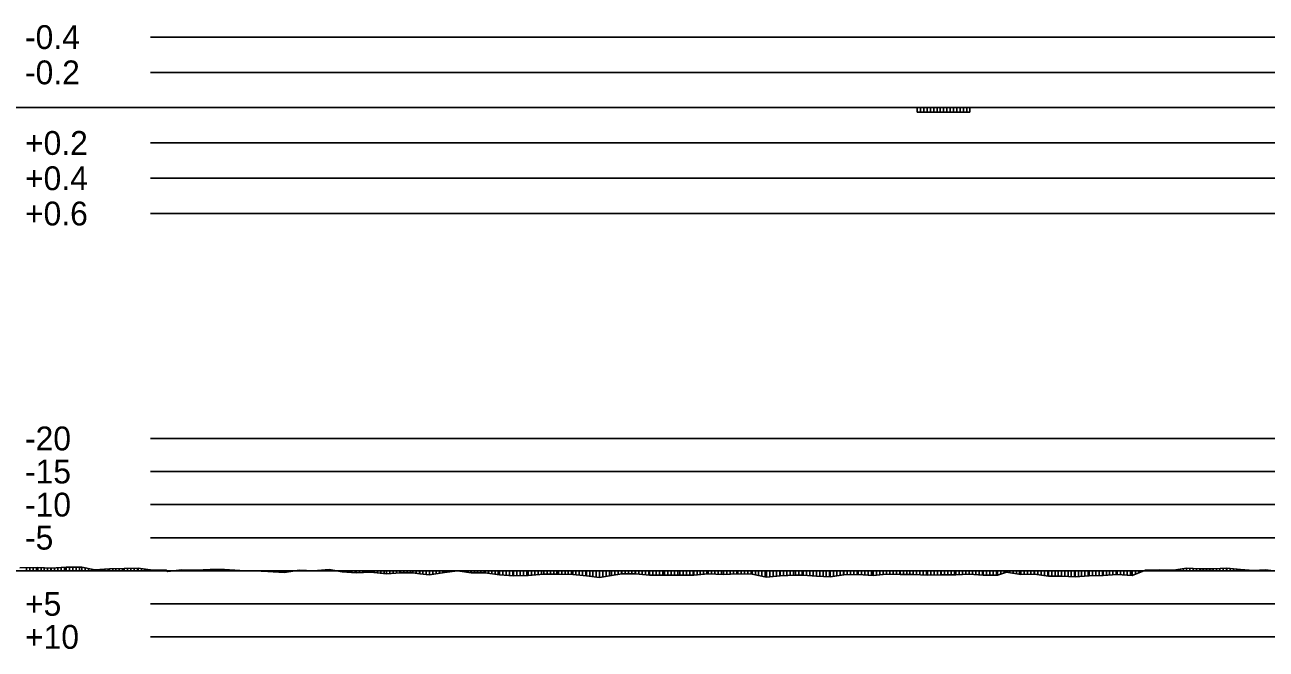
# Model space of a CAD drawing. Extents: x 2 to 10148, y 0 to 380.
# Drawn here: x 1152.5 to 1246.3, y 236.1 to 283.3 of the extents above; entities that cross this region are included whole.
import ezdxf

# ---------------------------------------------------------------- set-up
doc = ezdxf.new("R2010")
doc.units = 0
for name, color, linetype in [('POSUN_CARA', 7, 'Continuous'), ('POSUN_RASTR', 7, 'Continuous'), ('POSUN_TEXT', 7, 'Continuous'), ('ZRYCHL_CARA', 7, 'Continuous'), ('ZRYCHL_RASTR', 7, 'Continuous'), ('ZRYCHL_TEXT', 7, 'Continuous')]:
    doc.layers.add(name, color=color, linetype=linetype)

msp = doc.modelspace()

# ---------------------------------------------------------------- linework, layer by layer
at = {"layer": 'POSUN_CARA'}
for p, q in [((1152.119, 242.222), (1153.461, 242.257)), ((1152.619, 242), (1152.619, 242.235)), ((1152.869, 242), (1152.869, 242.241)), ((1153.119, 242), (1153.119, 242.248)), ((1153.369, 242), (1153.369, 242.255)), ((1153.461, 242.257), (1154.491, 242.196)), ((1153.461, 242), (1153.461, 242.257)), ((1153.711, 242), (1153.711, 242.242)), ((1153.961, 242), (1153.961, 242.227)), ((1154.211, 242), (1154.211, 242.213)), ((1154.461, 242), (1154.461, 242.198)), ((1154.491, 242.196), (1155.615, 242.273)), ((1154.491, 242), (1154.491, 242.196)), ((1154.741, 242), (1154.741, 242.213)), ((1154.991, 242), (1154.991, 242.23)), ((1155.241, 242), (1155.241, 242.248)), ((1155.491, 242), (1155.491, 242.265)), ((1155.615, 242.273), (1156.802, 242.264)), ((1155.615, 242), (1155.615, 242.273)), ((1155.865, 242), (1155.865, 242.271)), ((1156.115, 242), (1156.115, 242.269)), ((1156.365, 242), (1156.365, 242.267)), ((1156.615, 242), (1156.615, 242.265)), ((1156.802, 242.264), (1157.792, 242.077)), ((1156.802, 242), (1156.802, 242.264)), ((1157.052, 242), (1157.052, 242.217)), ((1157.302, 242), (1157.302, 242.169)), ((1157.792, 242.077), (1158.88, 242.143)), ((1158.88, 242.143), (1160.011, 242.176)), ((1158.88, 242), (1158.88, 242.143)), ((1159.13, 242), (1159.13, 242.15)), ((1159.38, 242), (1159.38, 242.158)), ((1159.63, 242), (1159.63, 242.165)), ((1159.88, 242), (1159.88, 242.172)), ((1160.011, 242.176), (1161.067, 242.202)), ((1160.011, 242), (1160.011, 242.176)), ((1160.261, 242), (1160.261, 242.182)), ((1160.511, 242), (1160.511, 242.189)), ((1160.761, 242), (1160.761, 242.195)), ((1161.011, 242), (1161.011, 242.201)), ((1161.067, 242.202), (1162.167, 242.055)), ((1161.067, 242), (1161.067, 242.202)), ((1161.317, 242), (1161.317, 242.169)), ((1239.345, 242.049), (1240.321, 242.202)), ((1240.095, 242), (1240.095, 242.166)), ((1240.321, 242.202), (1241.34, 242.158)), ((1240.321, 242), (1240.321, 242.202)), ((1240.571, 242), (1240.571, 242.191)), ((1240.821, 242), (1240.821, 242.18)), ((1241.071, 242), (1241.071, 242.169)), ((1241.321, 242), (1241.321, 242.159)), ((1241.34, 242.158), (1242.332, 242.151)), ((1241.34, 242), (1241.34, 242.158)), ((1241.59, 242), (1241.59, 242.156)), ((1241.84, 242), (1241.84, 242.155)), ((1242.09, 242), (1242.09, 242.153)), ((1242.332, 242.151), (1243.366, 242.19)), ((1242.332, 242), (1242.332, 242.151)), ((1242.582, 242), (1242.582, 242.161)), ((1242.832, 242), (1242.832, 242.17)), ((1243.082, 242), (1243.082, 242.179)), ((1243.332, 242), (1243.332, 242.189)), ((1243.366, 242.19), (1244.404, 242.103)), ((1243.366, 242), (1243.366, 242.19)), ((1243.616, 242), (1243.616, 242.169)), ((1243.866, 242), (1243.866, 242.148)), ((1157.552, 242), (1157.552, 242.122)), ((1157.792, 242), (1157.792, 242.077)), ((1158.042, 242), (1158.042, 242.092)), ((1158.292, 242), (1158.292, 242.107)), ((1158.542, 242), (1158.542, 242.122)), ((1158.792, 242), (1158.792, 242.137)), ((1161.567, 242), (1161.567, 242.135)), ((1161.817, 242), (1161.817, 242.102)), ((1162.067, 242), (1162.067, 242.069)), ((1162.167, 242.055), (1163.171, 242.071)), ((1162.167, 242), (1162.167, 242.055)), ((1162.417, 242), (1162.417, 242.059)), ((1162.667, 242), (1162.667, 242.063)), ((1162.917, 242), (1162.917, 242.067)), ((1163.167, 242), (1163.167, 242.071)), ((1163.171, 242.071), (1163.174, 241.999)), ((1163.171, 242), (1163.171, 242.071)), ((1163.233, 241.988), (1163.235, 242.031)), ((1163.233, 242), (1163.233, 241.988)), ((1163.235, 242.031), (1163.291, 241.925)), ((1163.235, 242), (1163.235, 242.031)), ((1163.291, 242), (1163.291, 241.925)), ((1163.291, 241.925), (1163.293, 241.95)), ((1163.293, 241.95), (1164.322, 242.082)), ((1163.293, 242), (1163.293, 241.95)), ((1163.543, 242), (1163.543, 241.982)), ((1163.793, 242), (1163.793, 242.014)), ((1164.043, 242), (1164.043, 242.046)), ((1164.293, 242), (1164.293, 242.078)), ((1164.322, 242.082), (1165.443, 242.052)), ((1164.322, 242), (1164.322, 242.082)), ((1164.572, 242), (1164.572, 242.075)), ((1164.822, 242), (1164.822, 242.069)), ((1165.072, 242), (1165.072, 242.062)), ((1165.322, 242), (1165.322, 242.055)), ((1165.443, 242.052), (1166.513, 242.103)), ((1165.443, 242), (1165.443, 242.052)), ((1165.693, 242), (1165.693, 242.064)), ((1165.943, 242), (1165.943, 242.076)), ((1166.193, 242), (1166.193, 242.088)), ((1166.443, 242), (1166.443, 242.1)), ((1166.513, 242.103), (1167.573, 242.097)), ((1166.513, 242), (1166.513, 242.103)), ((1166.763, 242), (1166.763, 242.102)), ((1167.013, 242), (1167.013, 242.1)), ((1167.263, 242), (1167.263, 242.099)), ((1167.513, 242), (1167.513, 242.098)), ((1167.573, 242.097), (1168.735, 242.013)), ((1167.573, 242), (1167.573, 242.097)), ((1167.823, 242), (1167.823, 242.079)), ((1168.073, 242), (1168.073, 242.061)), ((1168.323, 242), (1168.323, 242.043)), ((1168.573, 242), (1168.573, 242.025)), ((1169.835, 242), (1169.835, 241.989)), ((1169.835, 241.989), (1170.85, 241.936)), ((1170.085, 242), (1170.085, 241.976)), ((1170.335, 242), (1170.335, 241.963)), ((1170.585, 242), (1170.585, 241.95)), ((1170.835, 242), (1170.835, 241.937)), ((1170.85, 242), (1170.85, 241.936)), ((1170.85, 241.936), (1172.106, 241.873)), ((1171.1, 242), (1171.1, 241.923)), ((1171.35, 242), (1171.35, 241.911)), ((1171.6, 242), (1171.6, 241.898)), ((1171.85, 242), (1171.85, 241.886)), ((1172.1, 242), (1172.1, 241.873)), ((1172.106, 241.873), (1173.244, 242.053)), ((1172.106, 242), (1172.106, 241.873)), ((1172.356, 242), (1172.356, 241.913)), ((1172.606, 242), (1172.606, 241.952)), ((1172.856, 242), (1172.856, 241.992)), ((1173.106, 242), (1173.106, 242.032)), ((1173.244, 242.053), (1174.312, 241.999)), ((1173.244, 242), (1173.244, 242.053)), ((1173.494, 242), (1173.494, 242.041)), ((1173.744, 242), (1173.744, 242.028)), ((1173.994, 242), (1173.994, 242.015)), ((1174.244, 242), (1174.244, 242.002)), ((1174.312, 241.999), (1175.497, 242.089)), ((1174.312, 242), (1174.312, 241.999)), ((1174.562, 242), (1174.562, 242.018)), ((1174.812, 242), (1174.812, 242.037)), ((1175.062, 242), (1175.062, 242.056)), ((1175.312, 242), (1175.312, 242.075)), ((1175.497, 242.089), (1176.472, 241.911)), ((1175.497, 242), (1175.497, 242.089)), ((1175.747, 242), (1175.747, 242.044)), ((1175.997, 242), (1175.997, 241.998)), ((1176.247, 242), (1176.247, 241.952)), ((1176.472, 242), (1176.472, 241.911)), ((1176.472, 241.911), (1177.546, 241.846)), ((1176.722, 242), (1176.722, 241.896)), ((1176.972, 242), (1176.972, 241.88)), ((1177.222, 242), (1177.222, 241.865)), ((1177.472, 242), (1177.472, 241.85)), ((1177.546, 242), (1177.546, 241.846)), ((1177.546, 241.846), (1178.659, 241.901)), ((1177.796, 242), (1177.796, 241.858)), ((1178.046, 242), (1178.046, 241.871)), ((1178.296, 242), (1178.296, 241.883)), ((1178.546, 242), (1178.546, 241.896)), ((1178.659, 242), (1178.659, 241.901)), ((1178.659, 241.901), (1179.83, 241.759)), ((1178.909, 242), (1178.909, 241.871)), ((1179.159, 242), (1179.159, 241.841)), ((1179.409, 242), (1179.409, 241.81)), ((1179.659, 242), (1179.659, 241.78)), ((1179.83, 242), (1179.83, 241.759)), ((1179.83, 241.759), (1180.889, 241.847)), ((1180.08, 242), (1180.08, 241.78)), ((1180.33, 242), (1180.33, 241.8)), ((1180.58, 242), (1180.58, 241.821)), ((1180.83, 242), (1180.83, 241.842)), ((1180.889, 242), (1180.889, 241.847)), ((1180.889, 241.847), (1181.816, 241.832)), ((1181.139, 242), (1181.139, 241.843)), ((1181.389, 242), (1181.389, 241.839)), ((1181.639, 242), (1181.639, 241.835)), ((1181.816, 242), (1181.816, 241.832)), ((1181.816, 241.832), (1182.342, 241.768)), ((1182.066, 242), (1182.066, 241.801)), ((1182.316, 242), (1182.316, 241.771)), ((1182.342, 242), (1182.342, 241.768)), ((1182.342, 241.768), (1183.092, 241.692)), ((1182.592, 242), (1182.592, 241.742)), ((1182.842, 242), (1182.842, 241.717)), ((1183.092, 242), (1183.092, 241.692)), ((1183.092, 241.692), (1184.21, 241.863)), ((1183.342, 242), (1183.342, 241.73)), ((1183.592, 242), (1183.592, 241.769)), ((1183.842, 242), (1183.842, 241.807)), ((1184.092, 242), (1184.092, 241.845)), ((1184.21, 242), (1184.21, 241.863)), ((1184.21, 241.863), (1185.201, 241.986)), ((1184.46, 242), (1184.46, 241.894)), ((1184.71, 242), (1184.71, 241.925)), ((1184.96, 242), (1184.96, 241.956)), ((1185.201, 242), (1185.201, 241.986)), ((1185.201, 241.986), (1186.225, 241.838)), ((1185.451, 242), (1185.451, 241.95)), ((1185.701, 242), (1185.701, 241.914)), ((1185.951, 242), (1185.951, 241.877)), ((1186.201, 242), (1186.201, 241.841)), ((1186.225, 242), (1186.225, 241.838)), ((1186.225, 241.838), (1187.286, 241.849)), ((1186.475, 242), (1186.475, 241.841)), ((1186.725, 242), (1186.725, 241.843)), ((1186.975, 242), (1186.975, 241.846)), ((1187.225, 242), (1187.225, 241.848)), ((1187.286, 242), (1187.286, 241.849)), ((1187.286, 241.849), (1188.377, 241.688)), ((1187.536, 242), (1187.536, 241.812)), ((1187.786, 242), (1187.786, 241.775)), ((1188.036, 242), (1188.036, 241.738)), ((1188.286, 242), (1188.286, 241.701)), ((1188.377, 242), (1188.377, 241.688)), ((1188.377, 241.688), (1189.431, 241.611)), ((1188.627, 242), (1188.627, 241.67)), ((1188.877, 242), (1188.877, 241.651)), ((1189.127, 242), (1189.127, 241.633)), ((1189.377, 242), (1189.377, 241.615)), ((1189.431, 242), (1189.431, 241.611)), ((1189.431, 241.611), (1190.541, 241.653)), ((1189.681, 242), (1189.681, 241.62)), ((1189.931, 242), (1189.931, 241.63)), ((1190.181, 242), (1190.181, 241.639)), ((1190.431, 242), (1190.431, 241.649)), ((1190.541, 242), (1190.541, 241.653)), ((1190.541, 241.653), (1191.722, 241.743)), ((1190.791, 242), (1190.791, 241.672)), ((1191.041, 242), (1191.041, 241.691)), ((1191.291, 242), (1191.291, 241.71)), ((1191.541, 242), (1191.541, 241.729)), ((1191.722, 242), (1191.722, 241.743)), ((1191.722, 241.743), (1192.829, 241.738)), ((1191.972, 242), (1191.972, 241.742)), ((1192.222, 242), (1192.222, 241.741)), ((1192.472, 242), (1192.472, 241.74)), ((1192.722, 242), (1192.722, 241.739)), ((1192.829, 242), (1192.829, 241.738)), ((1192.829, 241.738), (1193.909, 241.707)), ((1193.079, 242), (1193.079, 241.731)), ((1193.329, 242), (1193.329, 241.724)), ((1193.579, 242), (1193.579, 241.716)), ((1193.829, 242), (1193.829, 241.709)), ((1193.909, 242), (1193.909, 241.707)), ((1193.909, 241.707), (1194.944, 241.626)), ((1194.159, 242), (1194.159, 241.687)), ((1194.409, 242), (1194.409, 241.668)), ((1194.659, 242), (1194.659, 241.649)), ((1194.909, 242), (1194.909, 241.629)), ((1194.944, 242), (1194.944, 241.626)), ((1194.944, 241.626), (1195.939, 241.492)), ((1195.194, 242), (1195.194, 241.593)), ((1195.444, 242), (1195.444, 241.559)), ((1195.694, 242), (1195.694, 241.525)), ((1195.939, 242), (1195.939, 241.492)), ((1195.939, 241.492), (1196.848, 241.647)), ((1196.189, 242), (1196.189, 241.535)), ((1196.439, 242), (1196.439, 241.577)), ((1196.689, 242), (1196.689, 241.62)), ((1196.848, 242), (1196.848, 241.647)), ((1196.848, 241.647), (1197.627, 241.768)), ((1197.098, 242), (1197.098, 241.686)), ((1197.348, 242), (1197.348, 241.724)), ((1197.598, 242), (1197.598, 241.763)), ((1197.627, 242), (1197.627, 241.768)), ((1197.627, 241.768), (1198.657, 241.761)), ((1197.877, 242), (1197.877, 241.766)), ((1198.127, 242), (1198.127, 241.764)), ((1198.377, 242), (1198.377, 241.763)), ((1198.627, 242), (1198.627, 241.761)), ((1198.657, 242), (1198.657, 241.761)), ((1198.657, 241.761), (1199.723, 241.666)), ((1198.907, 242), (1198.907, 241.738)), ((1199.157, 242), (1199.157, 241.716)), ((1199.407, 242), (1199.407, 241.694)), ((1199.657, 242), (1199.657, 241.672)), ((1199.723, 242), (1199.723, 241.666)), ((1199.723, 241.666), (1200.848, 241.663)), ((1199.973, 242), (1199.973, 241.665)), ((1200.223, 242), (1200.223, 241.664)), ((1200.473, 242), (1200.473, 241.664)), ((1200.723, 242), (1200.723, 241.663)), ((1200.848, 242), (1200.848, 241.663)), ((1200.848, 241.663), (1202.016, 241.665)), ((1201.098, 242), (1201.098, 241.663)), ((1201.348, 242), (1201.348, 241.664)), ((1201.598, 242), (1201.598, 241.664)), ((1201.848, 242), (1201.848, 241.664)), ((1202.016, 242), (1202.016, 241.665)), ((1202.016, 241.665), (1203.059, 241.665)), ((1202.266, 242), (1202.266, 241.665)), ((1202.516, 242), (1202.516, 241.665)), ((1202.766, 242), (1202.766, 241.665)), ((1203.016, 242), (1203.016, 241.665)), ((1203.059, 242), (1203.059, 241.665)), ((1203.059, 241.665), (1204.163, 241.774)), ((1203.309, 242), (1203.309, 241.69)), ((1203.559, 242), (1203.559, 241.715)), ((1203.809, 242), (1203.809, 241.739)), ((1204.059, 242), (1204.059, 241.764)), ((1204.163, 242), (1204.163, 241.774)), ((1204.163, 241.774), (1205.317, 241.708)), ((1204.413, 242), (1204.413, 241.76)), ((1204.663, 242), (1204.663, 241.746)), ((1204.913, 242), (1204.913, 241.731)), ((1205.163, 242), (1205.163, 241.717)), ((1205.317, 242), (1205.317, 241.708)), ((1205.317, 241.708), (1206.4, 241.776)), ((1205.567, 242), (1205.567, 241.724)), ((1205.817, 242), (1205.817, 241.739)), ((1206.067, 242), (1206.067, 241.755)), ((1206.317, 242), (1206.317, 241.77)), ((1206.4, 242), (1206.4, 241.776)), ((1206.4, 241.776), (1207.469, 241.745)), ((1206.65, 242), (1206.65, 241.768)), ((1206.9, 242), (1206.9, 241.761)), ((1207.15, 242), (1207.15, 241.754)), ((1207.4, 242), (1207.4, 241.747)), ((1207.469, 242), (1207.469, 241.745)), ((1207.469, 241.745), (1208.57, 241.528)), ((1207.719, 242), (1207.719, 241.695)), ((1207.969, 242), (1207.969, 241.646)), ((1208.219, 242), (1208.219, 241.597)), ((1208.469, 242), (1208.469, 241.548)), ((1208.57, 242), (1208.57, 241.528)), ((1208.57, 241.528), (1209.606, 241.616)), ((1208.82, 242), (1208.82, 241.549)), ((1209.07, 242), (1209.07, 241.57)), ((1209.32, 242), (1209.32, 241.592)), ((1209.57, 242), (1209.57, 241.613)), ((1209.606, 242), (1209.606, 241.616)), ((1209.606, 241.616), (1210.755, 241.664)), ((1209.856, 242), (1209.856, 241.626)), ((1210.106, 242), (1210.106, 241.637)), ((1210.356, 242), (1210.356, 241.647)), ((1210.606, 242), (1210.606, 241.658)), ((1210.755, 242), (1210.755, 241.664)), ((1210.755, 241.664), (1211.331, 241.669)), ((1211.005, 242), (1211.005, 241.666)), ((1211.255, 242), (1211.255, 241.669)), ((1211.331, 242), (1211.331, 241.669)), ((1211.331, 241.669), (1212.335, 241.594)), ((1211.581, 242), (1211.581, 241.65)), ((1211.831, 242), (1211.831, 241.632)), ((1212.081, 242), (1212.081, 241.613)), ((1212.331, 242), (1212.331, 241.594)), ((1212.335, 242), (1212.335, 241.594)), ((1212.335, 241.594), (1213.38, 241.547)), ((1212.585, 242), (1212.585, 241.583)), ((1212.835, 242), (1212.835, 241.571)), ((1213.085, 242), (1213.085, 241.56)), ((1213.335, 242), (1213.335, 241.549)), ((1213.38, 242), (1213.38, 241.547)), ((1213.38, 241.547), (1214.422, 241.699)), ((1213.63, 242), (1213.63, 241.583)), ((1213.88, 242), (1213.88, 241.62)), ((1214.13, 242), (1214.13, 241.657)), ((1214.38, 242), (1214.38, 241.693)), ((1214.422, 242), (1214.422, 241.699)), ((1214.422, 241.699), (1215.503, 241.714)), ((1214.672, 242), (1214.672, 241.703)), ((1214.922, 242), (1214.922, 241.706)), ((1215.172, 242), (1215.172, 241.709)), ((1215.422, 242), (1215.422, 241.712)), ((1215.503, 242), (1215.503, 241.714)), ((1215.503, 241.714), (1216.626, 241.631)), ((1215.753, 242), (1215.753, 241.695)), ((1216.003, 242), (1216.003, 241.677)), ((1216.253, 242), (1216.253, 241.659)), ((1216.503, 242), (1216.503, 241.64)), ((1216.626, 242), (1216.626, 241.631)), ((1216.626, 241.631), (1217.638, 241.754)), ((1216.876, 242), (1216.876, 241.662)), ((1217.126, 242), (1217.126, 241.692)), ((1217.376, 242), (1217.376, 241.723)), ((1217.626, 242), (1217.626, 241.753)), ((1217.638, 242), (1217.638, 241.754)), ((1217.638, 241.754), (1218.661, 241.719)), ((1217.888, 242), (1217.888, 241.746)), ((1218.138, 242), (1218.138, 241.737)), ((1218.388, 242), (1218.388, 241.729)), ((1218.638, 242), (1218.638, 241.72)), ((1218.661, 242), (1218.661, 241.719)), ((1218.661, 241.719), (1219.657, 241.708)), ((1218.911, 242), (1218.911, 241.717)), ((1219.161, 242), (1219.161, 241.714)), ((1219.411, 242), (1219.411, 241.711)), ((1219.657, 242), (1219.657, 241.708)), ((1219.657, 241.708), (1220.735, 241.663)), ((1219.907, 242), (1219.907, 241.698)), ((1220.157, 242), (1220.157, 241.687)), ((1220.407, 242), (1220.407, 241.677)), ((1220.657, 242), (1220.657, 241.667)), ((1220.735, 242), (1220.735, 241.663)), ((1220.735, 241.663), (1221.779, 241.692)), ((1220.985, 242), (1220.985, 241.67)), ((1221.235, 242), (1221.235, 241.677)), ((1221.485, 242), (1221.485, 241.684)), ((1221.735, 242), (1221.735, 241.691)), ((1221.779, 242), (1221.779, 241.692)), ((1221.779, 241.692), (1222.886, 241.696)), ((1222.029, 242), (1222.029, 241.693)), ((1222.279, 242), (1222.279, 241.693)), ((1222.529, 242), (1222.529, 241.694)), ((1222.779, 242), (1222.779, 241.695)), ((1222.886, 242), (1222.886, 241.696)), ((1222.886, 241.696), (1223.887, 241.735)), ((1223.136, 242), (1223.136, 241.706)), ((1223.386, 242), (1223.386, 241.715)), ((1223.636, 242), (1223.636, 241.725)), ((1223.886, 242), (1223.886, 241.735)), ((1223.887, 242), (1223.887, 241.735)), ((1223.887, 241.735), (1224.943, 241.655)), ((1224.137, 242), (1224.137, 241.716)), ((1224.387, 242), (1224.387, 241.697)), ((1224.637, 242), (1224.637, 241.678)), ((1224.887, 242), (1224.887, 241.659)), ((1224.943, 242), (1224.943, 241.655)), ((1224.943, 241.655), (1226.022, 241.669)), ((1225.193, 242), (1225.193, 241.658)), ((1225.443, 242), (1225.443, 241.661)), ((1225.693, 242), (1225.693, 241.665)), ((1225.943, 242), (1225.943, 241.668)), ((1226.022, 242), (1226.022, 241.669)), ((1226.022, 241.669), (1226.703, 241.884)), ((1226.272, 242), (1226.272, 241.748)), ((1226.522, 242), (1226.522, 241.827)), ((1226.703, 242), (1226.703, 241.884)), ((1226.703, 241.884), (1227.788, 241.709)), ((1226.953, 242), (1226.953, 241.844)), ((1227.203, 242), (1227.203, 241.803)), ((1227.453, 242), (1227.453, 241.763)), ((1227.703, 242), (1227.703, 241.722)), ((1227.788, 242), (1227.788, 241.709)), ((1227.788, 241.709), (1228.836, 241.734)), ((1228.038, 242), (1228.038, 241.715)), ((1228.288, 242), (1228.288, 241.721)), ((1228.538, 242), (1228.538, 241.727)), ((1228.788, 242), (1228.788, 241.733)), ((1228.836, 242), (1228.836, 241.734)), ((1228.836, 241.734), (1229.877, 241.602)), ((1229.086, 242), (1229.086, 241.702)), ((1229.336, 242), (1229.336, 241.671)), ((1229.586, 242), (1229.586, 241.639)), ((1229.836, 242), (1229.836, 241.607)), ((1229.877, 242), (1229.877, 241.602)), ((1229.877, 241.602), (1230.859, 241.594)), ((1230.127, 242), (1230.127, 241.6)), ((1230.377, 242), (1230.377, 241.598)), ((1230.627, 242), (1230.627, 241.596)), ((1230.859, 242), (1230.859, 241.594)), ((1230.859, 241.594), (1231.89, 241.533)), ((1231.109, 242), (1231.109, 241.579)), ((1231.359, 242), (1231.359, 241.564)), ((1231.609, 242), (1231.609, 241.55)), ((1231.859, 242), (1231.859, 241.535)), ((1231.89, 242), (1231.89, 241.533)), ((1231.89, 241.533), (1232.958, 241.626)), ((1232.14, 242), (1232.14, 241.555)), ((1232.39, 242), (1232.39, 241.577)), ((1232.64, 242), (1232.64, 241.599)), ((1232.89, 242), (1232.89, 241.621)), ((1232.958, 242), (1232.958, 241.626)), ((1232.958, 241.626), (1234.008, 241.641)), ((1233.208, 242), (1233.208, 241.63)), ((1233.458, 242), (1233.458, 241.633)), ((1233.708, 242), (1233.708, 241.636)), ((1233.958, 242), (1233.958, 241.64)), ((1234.008, 242), (1234.008, 241.641)), ((1234.008, 241.641), (1235.073, 241.73)), ((1234.258, 242), (1234.258, 241.662)), ((1234.508, 242), (1234.508, 241.682)), ((1234.758, 242), (1234.758, 241.703)), ((1235.008, 242), (1235.008, 241.724)), ((1235.073, 242), (1235.073, 241.73)), ((1235.073, 241.73), (1236.212, 241.654)), ((1235.323, 242), (1235.323, 241.713)), ((1235.573, 242), (1235.573, 241.697)), ((1235.823, 242), (1235.823, 241.68)), ((1236.073, 242), (1236.073, 241.664)), ((1236.212, 241.654), (1237.218, 242.055)), ((1236.212, 242), (1236.212, 241.654)), ((1236.462, 242), (1236.462, 241.754)), ((1236.712, 242), (1236.712, 241.854)), ((1236.962, 242), (1236.962, 241.953)), ((1237.212, 242), (1237.212, 242.053)), ((1237.218, 242.055), (1238.239, 242.066)), ((1237.218, 242), (1237.218, 242.055)), ((1237.468, 242), (1237.468, 242.058)), ((1237.718, 242), (1237.718, 242.061)), ((1237.968, 242), (1237.968, 242.063)), ((1238.218, 242), (1238.218, 242.066)), ((1238.239, 242.066), (1239.345, 242.049)), ((1238.239, 242), (1238.239, 242.066)), ((1238.489, 242), (1238.489, 242.062)), ((1238.739, 242), (1238.739, 242.058)), ((1238.989, 242), (1238.989, 242.054)), ((1239.239, 242), (1239.239, 242.05)), ((1239.345, 242), (1239.345, 242.049)), ((1239.595, 242), (1239.595, 242.088)), ((1239.845, 242), (1239.845, 242.127)), ((1244.116, 242), (1244.116, 242.127)), ((1244.366, 242), (1244.366, 242.106)), ((1244.404, 242.103), (1245.395, 242.023)), ((1244.404, 242), (1244.404, 242.103)), ((1244.654, 242), (1244.654, 242.083)), ((1244.904, 242), (1244.904, 242.062)), ((1245.154, 242), (1245.154, 242.042)), ((1245.39, 242.023), (1246.27, 242.066)), ((1245.39, 242), (1245.39, 242.023)), ((1245.64, 242), (1245.64, 242.035)), ((1245.89, 242), (1245.89, 242.047)), ((1246.14, 242), (1246.14, 242.06)), ((1246.27, 242.066), (1247.142, 241.975)), ((1246.27, 242), (1246.27, 242.066))]:
    msp.add_line(p, q, dxfattribs=at)
at = {"layer": 'POSUN_RASTR'}
for p, q in [((1162, 252), (1245.395, 252)), ((1245.39, 252), (1358, 252)), ((1162, 249.5), (1245.395, 249.5)), ((1245.39, 249.5), (1358, 249.5)), ((1162, 247), (1245.395, 247)), ((1245.39, 247), (1358, 247)), ((1162, 244.5), (1245.395, 244.5)), ((1245.39, 244.5), (1358, 244.5)), ((631.22, 242), (1245.395, 242)), ((1245.39, 242), (1850.829, 242)), ((1162, 239.5), (1245.395, 239.5)), ((1245.39, 239.5), (1358, 239.5)), ((1162, 237), (1245.395, 237)), ((1245.39, 237), (1358, 237))]:
    msp.add_line(p, q, dxfattribs=at)
at = {"layer": 'ZRYCHL_CARA'}
for p, q in [((631.22, 277), (1245.395, 277)), ((1219.954, 277), (1219.954, 276.672)), ((1219.954, 277), (1219.954, 276.672)), ((1220.204, 277), (1220.204, 276.672)), ((1220.454, 277), (1220.454, 276.672)), ((1220.704, 277), (1220.704, 276.672)), ((1220.954, 277), (1220.954, 276.672)), ((1221.204, 277), (1221.204, 276.672)), ((1221.454, 277), (1221.454, 276.672)), ((1221.704, 277), (1221.704, 276.672)), ((1221.954, 277), (1221.954, 276.672)), ((1222.204, 277), (1222.204, 276.672)), ((1222.454, 277), (1222.454, 276.672)), ((1222.704, 277), (1222.704, 276.672)), ((1222.954, 277), (1222.954, 276.672)), ((1223.204, 277), (1223.204, 276.672)), ((1223.454, 277), (1223.454, 276.672)), ((1223.704, 277), (1223.704, 276.672)), ((1223.924, 276.672), (1223.924, 277)), ((1245.39, 277), (1850.829, 277)), ((1219.954, 276.672), (1223.924, 276.672))]:
    msp.add_line(p, q, dxfattribs=at)
at = {"layer": 'ZRYCHL_RASTR'}
for p, q in [((1162, 282.333), (1245.395, 282.333)), ((1245.39, 282.333), (1369.417, 282.333)), ((1162, 279.667), (1245.395, 279.667)), ((1245.39, 279.667), (1369.367, 279.667)), ((1162, 274.333), (1245.395, 274.333)), ((1245.39, 274.333), (1369.392, 274.333)), ((1162, 271.667), (1245.395, 271.667)), ((1245.39, 271.667), (1369.367, 271.667)), ((1162, 269), (1245.395, 269)), ((1245.39, 269), (1369.342, 269))]:
    msp.add_line(p, q, dxfattribs=at)

# ---------------------------------------------------------------- texts
at = {"layer": 'POSUN_TEXT'}
for s, p in [('-20', (1152.5, 251.1)), ('-15', (1152.5, 248.6)), ('-10', (1152.5, 246.1)), ('-5', (1152.5, 243.6)), ('+5', (1152.5, 238.6)), ('+10', (1152.5, 236.1))]:
    msp.add_text(s, height=1.8, dxfattribs=at).set_placement(p)
at = {"layer": 'ZRYCHL_TEXT'}
for s, p in [('-0.4', (1152.5, 281.433)), ('-0.2', (1152.5, 278.767)), ('+0.2', (1152.5, 273.433)), ('+0.4', (1152.5, 270.767)), ('+0.6', (1152.5, 268.1))]:
    msp.add_text(s, height=1.8, dxfattribs=at).set_placement(p)

doc.saveas('drawing.dxf')
